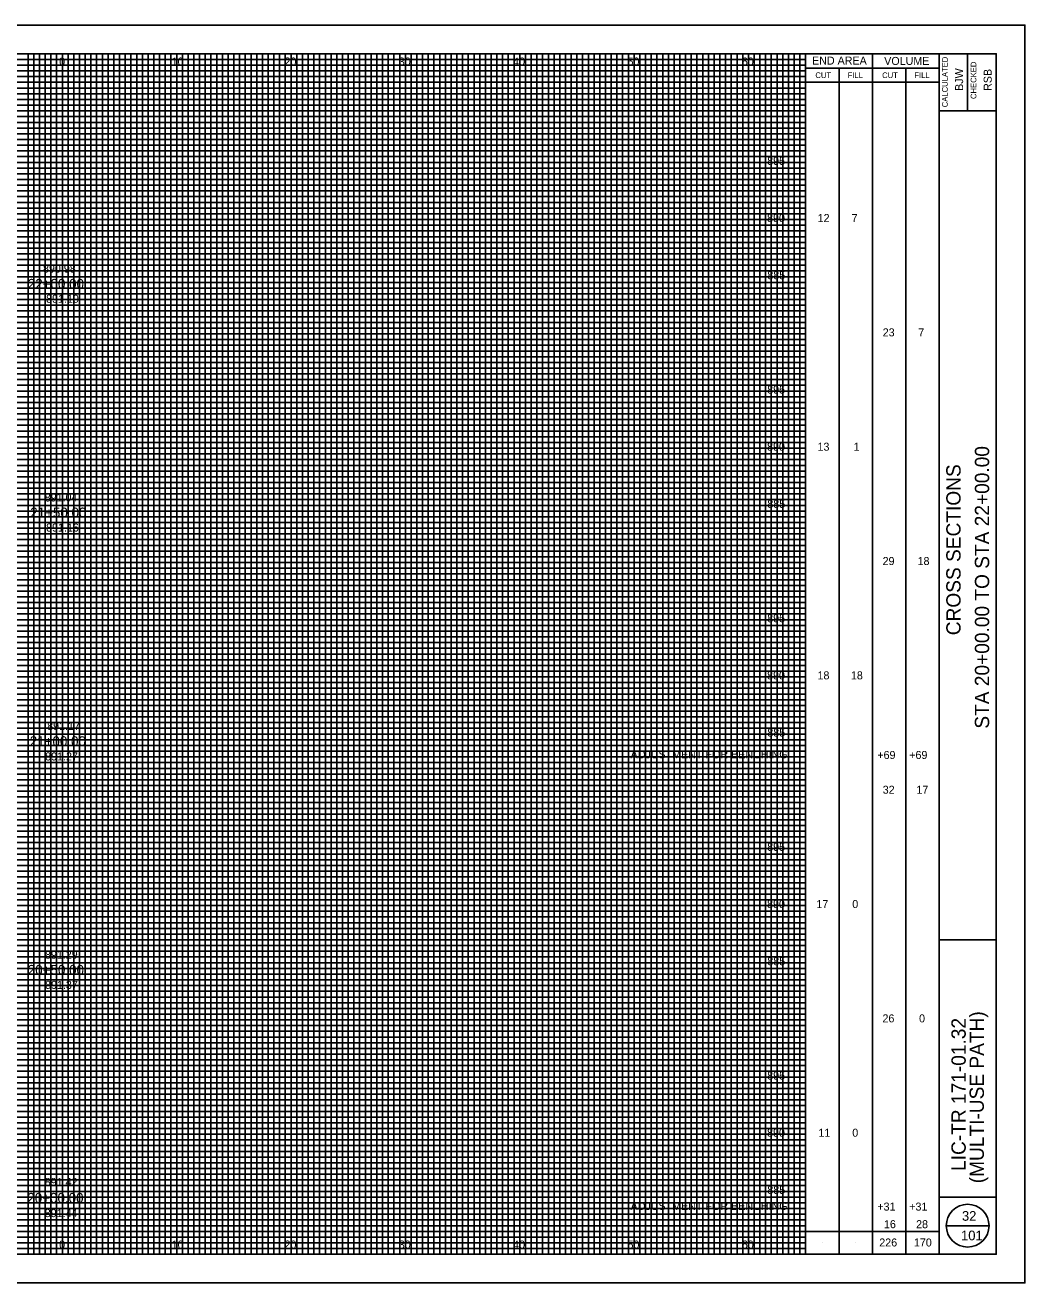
# Model space of a CAD drawing. Extents: x -10 to 160, y -2 to 2522.
# Drawn here: x 72.6 to 160, y 457.5 to 567.5 of the extents above; entities that cross this region are included whole.
import ezdxf

# ---------------------------------------------------------------- set-up
doc = ezdxf.new("R2010")
doc.units = 0
for name, color, linetype in [('GK_Cells', 7, 'Continuous'), ('GK_Patterns', 7, 'Continuous'), ('TX_P_10', 7, 'Continuous'), ('TX_X_10', 7, 'Continuous'), ('XS_P_Finished_Grade_Seeded', 7, 'Continuous'), ('XS_P_Pavt_Surface', 7, 'Continuous'), ('XS_P_Subgrade', 7, 'Continuous'), ('XS_X_Ground_Line', 7, 'Continuous')]:
    doc.layers.add(name, color=color, linetype=linetype)

msp = doc.modelspace()

# ---------------------------------------------------------------- linework, layer by layer
at = {"layer": 'GK_Cells'}
msp.add_lwpolyline([(-10, 457.5), (160, 457.5), (160, 567.5), (-10, 567.5)], close=True, dxfattribs=at)
at = {"layer": 'TX_P_10'}
for p, q in [((140.83, 460), (140.83, 565)), ((146.67, 460), (146.67, 565)), ((140.83, 563.75), (152.5, 563.75)), ((143.75, 460), (143.75, 563.75)), ((149.58, 460), (149.58, 563.75)), ((140.83, 562.5), (152.5, 562.5)), ((153.12, 462.5), (156.88, 462.5)), ((140.83, 462), (152.5, 462)), ((142.29, 461), (142.29, 461)), ((145.21, 461), (145.21, 461)), ((148.12, 461), (148.12, 461)), ((151.04, 461), (151.04, 461))]:
    msp.add_line(p, q, dxfattribs=at)
msp.add_circle((155, 462.5), 1.87, dxfattribs=at)
at = {"layer": 'TX_X_10'}
for p, q in [((75.83, 460), (75.83, 565)), ((80.83, 460), (80.83, 565)), ((85.83, 460), (85.83, 565)), ((90.83, 460), (90.83, 565)), ((95.83, 460), (95.83, 565)), ((100.83, 460), (100.83, 565)), ((105.83, 460), (105.83, 565)), ((110.83, 460), (110.83, 565)), ((115.83, 460), (115.83, 565)), ((120.83, 460), (120.83, 565)), ((125.83, 460), (125.83, 565)), ((130.83, 460), (130.83, 565)), ((135.83, 460), (135.83, 565)), ((5.83, 560), (140.83, 560)), ((5.83, 555), (140.83, 555)), ((5.83, 550), (140.83, 550)), ((5.83, 545), (140.83, 545)), ((5.83, 540), (140.83, 540)), ((5.83, 535), (140.83, 535)), ((5.83, 530), (140.83, 530)), ((5.83, 525), (140.83, 525)), ((5.83, 520), (140.83, 520)), ((5.83, 515), (140.83, 515)), ((5.83, 510), (140.83, 510)), ((5.83, 505), (140.83, 505)), ((5.83, 500), (140.83, 500)), ((5.83, 495), (140.83, 495)), ((5.83, 490), (140.83, 490)), ((5.83, 485), (140.83, 485)), ((5.83, 480), (140.83, 480)), ((5.83, 475), (140.83, 475)), ((5.83, 470), (140.83, 470)), ((5.83, 465), (140.83, 465))]:
    msp.add_line(p, q, dxfattribs=at)
at = {"layer": 'XS_P_Pavt_Surface'}
for p, q in [((152.5, 460), (152.5, 565)), ((155, 565), (155, 560)), ((152.5, 560), (157.5, 560)), ((152.5, 487.5), (157.5, 487.5)), ((152.5, 465), (157.5, 465))]:
    msp.add_line(p, q, dxfattribs=at)
msp.add_lwpolyline([(0, 565), (157.5, 565), (157.5, 460), (0, 460)], close=True, dxfattribs=at)
at = {"layer": 'XS_X_Ground_Line'}
for p, q in [((5.83, 564.5), (140.83, 564.5)), ((72.83, 460), (72.83, 565)), ((73.33, 460), (73.33, 565)), ((73.83, 460), (73.83, 565)), ((74.33, 460), (74.33, 565)), ((74.83, 460), (74.83, 565)), ((75.33, 460), (75.33, 565)), ((76.33, 460), (76.33, 565)), ((76.83, 460), (76.83, 565)), ((77.33, 460), (77.33, 565)), ((77.83, 460), (77.83, 565)), ((78.33, 460), (78.33, 565)), ((78.83, 460), (78.83, 565)), ((79.33, 460), (79.33, 565)), ((79.83, 460), (79.83, 565)), ((80.33, 460), (80.33, 565)), ((81.33, 460), (81.33, 565)), ((81.83, 460), (81.83, 565)), ((82.33, 460), (82.33, 565)), ((82.83, 460), (82.83, 565)), ((83.33, 460), (83.33, 565)), ((83.83, 460), (83.83, 565)), ((84.33, 460), (84.33, 565)), ((84.83, 460), (84.83, 565)), ((85.33, 460), (85.33, 565)), ((86.33, 460), (86.33, 565)), ((86.83, 460), (86.83, 565)), ((87.33, 460), (87.33, 565)), ((87.83, 460), (87.83, 565)), ((88.33, 460), (88.33, 565)), ((88.83, 460), (88.83, 565)), ((89.33, 460), (89.33, 565)), ((89.83, 460), (89.83, 565)), ((90.33, 460), (90.33, 565)), ((91.33, 460), (91.33, 565)), ((91.83, 460), (91.83, 565)), ((92.33, 460), (92.33, 565)), ((92.83, 460), (92.83, 565)), ((93.33, 460), (93.33, 565)), ((93.83, 460), (93.83, 565)), ((94.33, 460), (94.33, 565)), ((94.83, 460), (94.83, 565)), ((95.33, 460), (95.33, 565)), ((96.33, 460), (96.33, 565)), ((96.83, 460), (96.83, 565)), ((97.33, 460), (97.33, 565)), ((97.83, 460), (97.83, 565)), ((98.33, 460), (98.33, 565)), ((98.83, 460), (98.83, 565)), ((99.33, 460), (99.33, 565)), ((99.83, 460), (99.83, 565)), ((100.33, 460), (100.33, 565)), ((101.33, 460), (101.33, 565)), ((101.83, 460), (101.83, 565)), ((102.33, 460), (102.33, 565)), ((102.83, 460), (102.83, 565)), ((103.33, 460), (103.33, 565)), ((103.83, 460), (103.83, 565)), ((104.33, 460), (104.33, 565)), ((104.83, 460), (104.83, 565)), ((105.33, 460), (105.33, 565)), ((106.33, 460), (106.33, 565)), ((106.83, 460), (106.83, 565)), ((107.33, 460), (107.33, 565)), ((107.83, 460), (107.83, 565)), ((108.33, 460), (108.33, 565)), ((108.83, 460), (108.83, 565)), ((109.33, 460), (109.33, 565)), ((109.83, 460), (109.83, 565)), ((110.33, 460), (110.33, 565)), ((111.33, 460), (111.33, 565)), ((111.83, 460), (111.83, 565)), ((112.33, 460), (112.33, 565)), ((112.83, 460), (112.83, 565)), ((113.33, 460), (113.33, 565)), ((113.83, 460), (113.83, 565)), ((114.33, 460), (114.33, 565)), ((114.83, 460), (114.83, 565)), ((115.33, 460), (115.33, 565)), ((116.33, 460), (116.33, 565)), ((116.83, 460), (116.83, 565)), ((117.33, 460), (117.33, 565)), ((117.83, 460), (117.83, 565)), ((118.33, 460), (118.33, 565)), ((118.83, 460), (118.83, 565)), ((119.33, 460), (119.33, 565)), ((119.83, 460), (119.83, 565)), ((120.33, 460), (120.33, 565)), ((121.33, 460), (121.33, 565)), ((121.83, 460), (121.83, 565)), ((122.33, 460), (122.33, 565)), ((122.83, 460), (122.83, 565)), ((123.33, 460), (123.33, 565)), ((123.83, 460), (123.83, 565)), ((124.33, 460), (124.33, 565)), ((124.83, 460), (124.83, 565)), ((125.33, 460), (125.33, 565)), ((126.33, 460), (126.33, 565)), ((126.83, 460), (126.83, 565)), ((127.33, 460), (127.33, 565)), ((127.83, 460), (127.83, 565)), ((128.33, 460), (128.33, 565)), ((128.83, 460), (128.83, 565)), ((129.33, 460), (129.33, 565)), ((129.83, 460), (129.83, 565)), ((130.33, 460), (130.33, 565)), ((131.33, 460), (131.33, 565)), ((131.83, 460), (131.83, 565)), ((132.33, 460), (132.33, 565)), ((132.83, 460), (132.83, 565)), ((133.33, 460), (133.33, 565)), ((133.83, 460), (133.83, 565)), ((134.33, 460), (134.33, 565)), ((134.83, 460), (134.83, 565)), ((135.33, 460), (135.33, 565)), ((136.33, 460), (136.33, 565)), ((136.83, 460), (136.83, 565)), ((137.33, 460), (137.33, 565)), ((137.83, 460), (137.83, 565)), ((138.33, 460), (138.33, 565)), ((138.83, 460), (138.83, 565)), ((139.33, 460), (139.33, 565)), ((139.83, 460), (139.83, 565)), ((140.33, 460), (140.33, 565)), ((5.83, 564), (140.83, 564)), ((5.83, 563.5), (140.83, 563.5)), ((5.83, 563), (140.83, 563)), ((5.83, 562.5), (140.83, 562.5)), ((5.83, 562), (140.83, 562)), ((5.83, 561.5), (140.83, 561.5)), ((5.83, 561), (140.83, 561)), ((5.83, 560.5), (140.83, 560.5)), ((5.83, 559.5), (140.83, 559.5)), ((5.83, 559), (140.83, 559)), ((5.83, 558.5), (140.83, 558.5)), ((5.83, 558), (140.83, 558)), ((5.83, 557.5), (140.83, 557.5)), ((5.83, 557), (140.83, 557)), ((5.83, 556.5), (140.83, 556.5)), ((5.83, 556), (140.83, 556)), ((5.83, 555.5), (140.83, 555.5)), ((5.83, 554.5), (140.83, 554.5)), ((5.83, 554), (140.83, 554)), ((5.83, 553.5), (140.83, 553.5)), ((5.83, 553), (140.83, 553)), ((5.83, 552.5), (140.83, 552.5)), ((5.83, 552), (140.83, 552)), ((5.83, 551.5), (140.83, 551.5)), ((5.83, 551), (140.83, 551)), ((5.83, 550.5), (140.83, 550.5)), ((5.83, 549.5), (140.83, 549.5)), ((5.83, 549), (140.83, 549)), ((5.83, 548.5), (140.83, 548.5)), ((5.83, 548), (140.83, 548)), ((5.83, 547.5), (140.83, 547.5)), ((5.83, 547), (140.83, 547)), ((5.83, 546.5), (140.83, 546.5)), ((5.83, 546), (140.83, 546)), ((5.83, 545.5), (140.83, 545.5)), ((5.83, 544.5), (140.83, 544.5)), ((5.83, 544), (140.83, 544)), ((5.83, 543.5), (140.83, 543.5)), ((5.83, 543), (140.83, 543)), ((5.83, 542.5), (140.83, 542.5)), ((5.83, 542), (140.83, 542)), ((5.83, 541.5), (140.83, 541.5)), ((5.83, 541), (140.83, 541)), ((5.83, 540.5), (140.83, 540.5)), ((5.83, 539.5), (140.83, 539.5)), ((5.83, 539), (140.83, 539)), ((5.83, 538.5), (140.83, 538.5)), ((5.83, 538), (140.83, 538)), ((5.83, 537.5), (140.83, 537.5)), ((5.83, 537), (140.83, 537)), ((5.83, 536.5), (140.83, 536.5)), ((5.83, 536), (140.83, 536)), ((5.83, 535.5), (140.83, 535.5)), ((5.83, 534.5), (140.83, 534.5)), ((5.83, 534), (140.83, 534)), ((5.83, 533.5), (140.83, 533.5)), ((5.83, 533), (140.83, 533)), ((5.83, 532.5), (140.83, 532.5)), ((5.83, 532), (140.83, 532)), ((5.83, 531.5), (140.83, 531.5)), ((5.83, 531), (140.83, 531)), ((5.83, 530.5), (140.83, 530.5)), ((5.83, 529.5), (140.83, 529.5)), ((5.83, 529), (140.83, 529)), ((5.83, 528.5), (140.83, 528.5)), ((5.83, 528), (140.83, 528)), ((5.83, 527.5), (140.83, 527.5)), ((5.83, 527), (140.83, 527)), ((5.83, 526.5), (140.83, 526.5)), ((5.83, 526), (140.83, 526)), ((5.83, 525.5), (140.83, 525.5)), ((5.83, 524.5), (140.83, 524.5)), ((5.83, 524), (140.83, 524)), ((5.83, 523.5), (140.83, 523.5)), ((5.83, 523), (140.83, 523)), ((5.83, 522.5), (140.83, 522.5)), ((5.83, 522), (140.83, 522)), ((5.83, 521.5), (140.83, 521.5)), ((5.83, 521), (140.83, 521)), ((5.83, 520.5), (140.83, 520.5)), ((5.83, 519.5), (140.83, 519.5)), ((5.83, 519), (140.83, 519)), ((5.83, 518.5), (140.83, 518.5)), ((5.83, 518), (140.83, 518)), ((5.83, 517.5), (140.83, 517.5)), ((5.83, 517), (140.83, 517)), ((5.83, 516.5), (140.83, 516.5)), ((5.83, 516), (140.83, 516)), ((5.83, 515.5), (140.83, 515.5)), ((5.83, 514.5), (140.83, 514.5)), ((5.83, 514), (140.83, 514)), ((5.83, 513.5), (140.83, 513.5)), ((5.83, 513), (140.83, 513)), ((5.83, 512.5), (140.83, 512.5)), ((5.83, 512), (140.83, 512)), ((5.83, 511.5), (140.83, 511.5)), ((5.83, 511), (140.83, 511)), ((5.83, 510.5), (140.83, 510.5)), ((5.83, 509.5), (140.83, 509.5)), ((5.83, 509), (140.83, 509)), ((5.83, 508.5), (140.83, 508.5)), ((5.83, 508), (140.83, 508)), ((5.83, 507.5), (140.83, 507.5)), ((5.83, 507), (140.83, 507)), ((5.83, 506.5), (140.83, 506.5)), ((5.83, 506), (140.83, 506)), ((5.83, 505.5), (140.83, 505.5)), ((5.83, 504.5), (140.83, 504.5)), ((5.83, 504), (140.83, 504)), ((5.83, 503.5), (140.83, 503.5)), ((5.83, 503), (140.83, 503)), ((5.83, 502.5), (140.83, 502.5)), ((5.83, 502), (140.83, 502)), ((5.83, 501.5), (140.83, 501.5)), ((5.83, 501), (140.83, 501)), ((5.83, 500.5), (140.83, 500.5)), ((5.83, 499.5), (140.83, 499.5)), ((5.83, 499), (140.83, 499)), ((5.83, 498.5), (140.83, 498.5)), ((5.83, 498), (140.83, 498)), ((5.83, 497.5), (140.83, 497.5)), ((5.83, 497), (140.83, 497)), ((5.83, 496.5), (140.83, 496.5)), ((5.83, 496), (140.83, 496)), ((5.83, 495.5), (140.83, 495.5)), ((5.83, 494.5), (140.83, 494.5)), ((5.83, 494), (140.83, 494)), ((5.83, 493.5), (140.83, 493.5)), ((5.83, 493), (140.83, 493)), ((5.83, 492.5), (140.83, 492.5)), ((5.83, 492), (140.83, 492)), ((5.83, 491.5), (140.83, 491.5)), ((5.83, 491), (140.83, 491)), ((5.83, 490.5), (140.83, 490.5)), ((5.83, 489.5), (140.83, 489.5)), ((5.83, 489), (140.83, 489)), ((5.83, 488.5), (140.83, 488.5)), ((5.83, 488), (140.83, 488)), ((5.83, 487.5), (140.83, 487.5)), ((5.83, 487), (140.83, 487)), ((5.83, 486.5), (140.83, 486.5)), ((5.83, 486), (140.83, 486)), ((5.83, 485.5), (140.83, 485.5)), ((5.83, 484.5), (140.83, 484.5)), ((5.83, 484), (140.83, 484)), ((5.83, 483.5), (140.83, 483.5)), ((5.83, 483), (140.83, 483)), ((5.83, 482.5), (140.83, 482.5)), ((5.83, 482), (140.83, 482)), ((5.83, 481.5), (140.83, 481.5)), ((5.83, 481), (140.83, 481)), ((5.83, 480.5), (140.83, 480.5)), ((5.83, 479.5), (140.83, 479.5)), ((5.83, 479), (140.83, 479)), ((5.83, 478.5), (140.83, 478.5)), ((5.83, 478), (140.83, 478)), ((5.83, 477.5), (140.83, 477.5)), ((5.83, 477), (140.83, 477)), ((5.83, 476.5), (140.83, 476.5)), ((5.83, 476), (140.83, 476)), ((5.83, 475.5), (140.83, 475.5)), ((5.83, 474.5), (140.83, 474.5)), ((5.83, 474), (140.83, 474)), ((5.83, 473.5), (140.83, 473.5)), ((5.83, 473), (140.83, 473)), ((5.83, 472.5), (140.83, 472.5)), ((5.83, 472), (140.83, 472)), ((5.83, 471.5), (140.83, 471.5)), ((5.83, 471), (140.83, 471)), ((5.83, 470.5), (140.83, 470.5)), ((5.83, 469.5), (140.83, 469.5)), ((5.83, 469), (140.83, 469)), ((5.83, 468.5), (140.83, 468.5)), ((5.83, 468), (140.83, 468)), ((5.83, 467.5), (140.83, 467.5)), ((5.83, 467), (140.83, 467)), ((5.83, 466.5), (140.83, 466.5)), ((5.83, 466), (140.83, 466)), ((5.83, 465.5), (140.83, 465.5)), ((5.83, 464.5), (140.83, 464.5)), ((5.83, 464), (140.83, 464)), ((5.83, 463.5), (140.83, 463.5)), ((5.83, 463), (140.83, 463)), ((5.83, 462.5), (140.83, 462.5)), ((5.83, 462), (140.83, 462)), ((5.83, 461.5), (140.83, 461.5)), ((5.83, 461), (140.83, 461)), ((5.83, 460.5), (140.83, 460.5))]:
    msp.add_line(p, q, dxfattribs=at)

# ---------------------------------------------------------------- texts
at = {"layer": 'GK_Patterns'}
for s, height, p in [('0', 0.7, (75.55, 563.97)), ('0', 0.7, (75.55, 563.97)), ('10', 0.7, (85.39, 563.97)), ('20', 0.7, (95.26, 563.97)), ('30', 0.7, (105.25, 563.97)), ('40', 0.7, (115.25, 563.97)), ('50', 0.7, (125.25, 563.97)), ('60', 0.7, (135.25, 563.97)), ('895', 0.7, (137.47, 555.28)), ('890', 0.7, (137.46, 550.28)), ('12', 0.7, (141.88, 550.28)), ('7', 0.7, (144.85, 550.28)), ('885', 0.7, (137.48, 545.28)), ('22+00.00', 0.875, (72.81, 544.43)), ('23', 0.7, (147.57, 540.28)), ('7', 0.7, (150.68, 540.28)), ('895', 0.7, (137.47, 535.28)), ('890', 0.7, (137.46, 530.28)), ('13', 0.7, (141.87, 530.28)), ('1', 0.7, (145.03, 530.28)), ('885', 0.7, (137.48, 525.28)), ('21+50.00', 0.875, (73.02, 524.43)), ('29', 0.7, (147.56, 520.28)), ('18', 0.7, (150.62, 520.28)), ('895', 0.7, (137.47, 515.28)), ('890', 0.7, (137.46, 510.28)), ('18', 0.7, (141.87, 510.28)), ('18', 0.7, (144.79, 510.28)), ('21+00.00', 0.875, (72.98, 504.43)), ('885', 0.7, (137.48, 505.28)), ('ADJUSTMENT FOR BENCHING', 0.7, (125.52, 503.37)), ('+69', 0.7, (147.1, 503.32)), ('+69', 0.7, (149.89, 503.32)), ('32', 0.7, (147.57, 500.28)), ('17', 0.7, (150.52, 500.28)), ('895', 0.7, (137.47, 495.28)), ('890', 0.7, (137.46, 490.28)), ('17', 0.7, (141.77, 490.28)), ('0', 0.7, (144.91, 490.28)), ('20+50.00', 0.875, (72.81, 484.43)), ('885', 0.7, (137.48, 485.28)), ('26', 0.7, (147.55, 480.28)), ('0', 0.7, (150.75, 480.28)), ('895', 0.7, (137.47, 475.28)), ('890', 0.7, (137.46, 470.28)), ('11', 0.7, (141.95, 470.28)), ('0', 0.7, (144.91, 470.28)), ('20+00.00', 0.875, (72.77, 464.49)), ('885', 0.7, (137.48, 465.28)), ('ADJUSTMENT FOR BENCHING', 0.7, (125.52, 463.87)), ('+31', 0.7, (147.1, 463.82)), ('+31', 0.7, (149.89, 463.82)), ('16', 0.7, (147.68, 462.28)), ('28', 0.7, (150.49, 462.28)), ('0', 0.7, (75.55, 460.5)), ('0', 0.7, (75.55, 460.5)), ('10', 0.7, (85.39, 460.5)), ('20', 0.7, (95.26, 460.5)), ('30', 0.7, (105.25, 460.5)), ('40', 0.7, (115.25, 460.5)), ('50', 0.7, (125.25, 460.5)), ('60', 0.7, (135.25, 460.5)), ('226', 0.7, (147.27, 460.68)), ('170', 0.7, (150.3, 460.68))]:
    msp.add_text(s, height=height, dxfattribs=at).set_placement(p)
at = {"layer": 'TX_P_10'}
for s, height, p in [('END AREA', 0.7, (141.39, 564.05)), ('VOLUME', 0.7, (147.7, 564.02)), ('CUT', 0.5, (141.68, 562.87)), ('FILL', 0.5, (144.5, 562.87)), ('CUT', 0.5, (147.52, 562.87)), ('FILL', 0.5, (150.34, 562.87)), ('32', 0.85, (154.5, 462.93)), ('101', 0.85, (154.42, 461.22))]:
    msp.add_text(s, height=height, dxfattribs=at).set_placement(p)
for s, height, p in [('CALCULATED', 0.5, (153.26, 560.32)), ('BJW', 0.7, (154.6, 561.75)), ('CHECKED', 0.5, (155.76, 561.04)), ('RSB', 0.7, (157.1, 561.75)), ('STA 20+00.00 TO STA 22+00.00', 1.25, (156.88, 505.97)), ('CROSS SECTIONS', 1.25, (154.38, 514.14)), ('(MULTI-USE PATH)', 1.25, (156.42, 466.21)), ('LIC-TR 171-01.32', 1.25, (154.83, 467.29))]:
    msp.add_text(s, height=height, rotation=90, dxfattribs=at).set_placement(p)
at = {"layer": 'XS_P_Finished_Grade_Seeded'}
for s, p in [('891.10', (74.41, 543.22)), ('891.16', (74.41, 523.21)), ('891.27', (74.33, 503.19)), ('891.37', (74.32, 483.21)), ('891.44', (74.29, 463.25))]:
    msp.add_text(s, height=0.7, dxfattribs=at).set_placement(p)
at = {"layer": 'XS_P_Subgrade'}
for s, p in [('890.98', (74.14, 545.86)), ('891.04', (74.29, 525.84)), ('891.17', (74.5, 505.85)), ('891.29', (74.31, 485.85)), ('891.42', (74.29, 465.97))]:
    msp.add_text(s, height=0.7, dxfattribs=at).set_placement(p)

doc.saveas('drawing.dxf')
